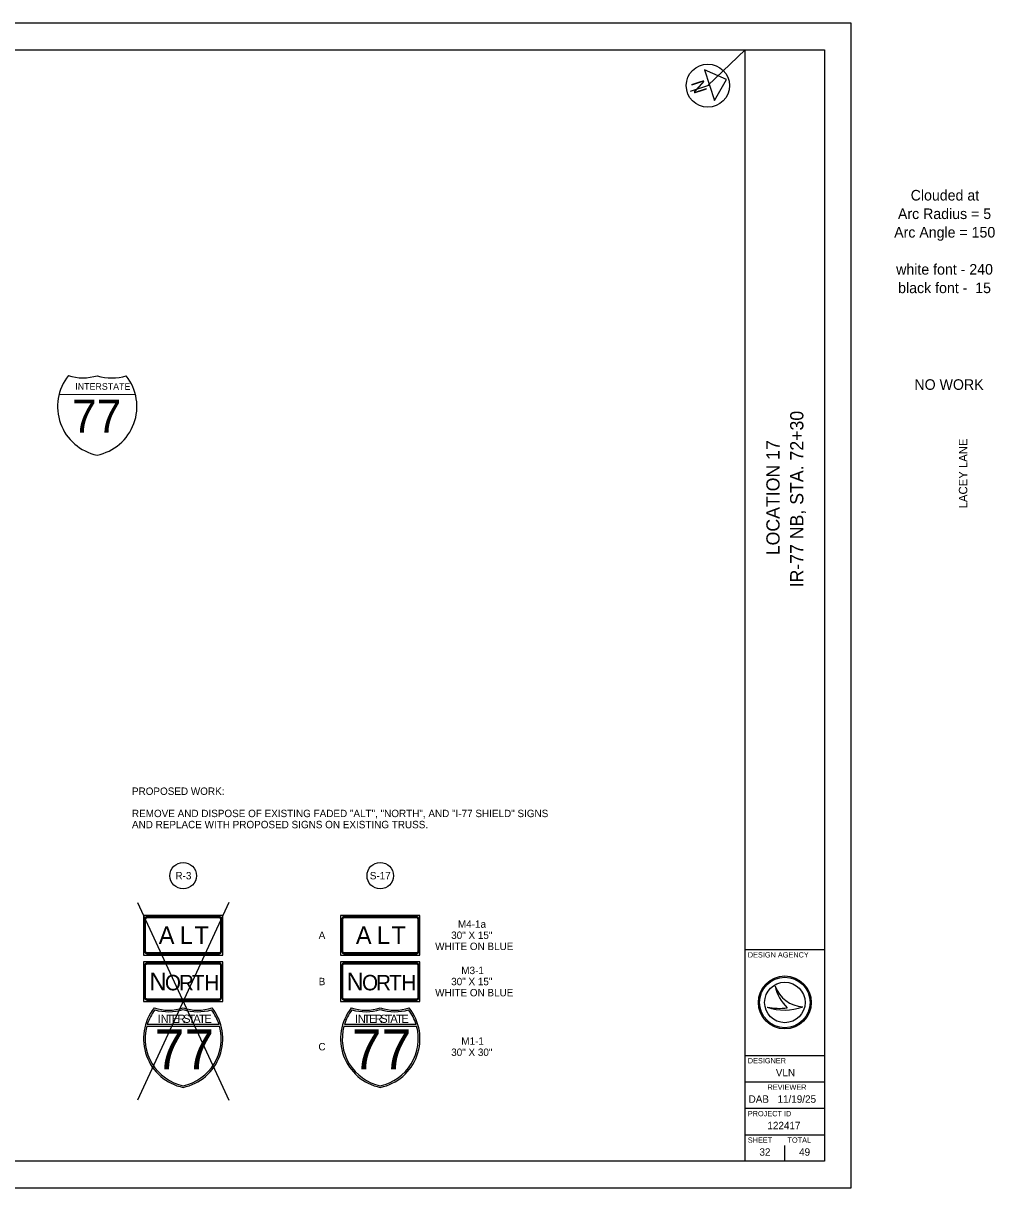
# Model space of a CAD drawing. Extents: x 0 to 734, y 0 to 440.
# Drawn here: x 367.2 to 734.3, y 0 to 440 of the extents above; entities that cross this region are included whole.
import ezdxf

# ---------------------------------------------------------------- set-up
doc = ezdxf.new("R2010")
doc.units = 0
for name, color, linetype in [('Default', 7, 'Continuous'), ('SC_Scratch1', 7, 'Continuous'), ('SH_Border', 7, 'Continuous'), ('SH_Cut_Line', 7, 'Continuous'), ('SH_Data', 7, 'Continuous'), ('SH_Masking', 7, 'Continuous'), ('SH_Text', 7, 'Continuous'), ('SN_P_Text', 7, 'Continuous'), ('SN_X_Public', 7, 'Continuous')]:
    doc.layers.add(name, color=color, linetype=linetype)

msp = doc.modelspace()

# ---------------------------------------------------------------- linework, layer by layer
at = {"layer": 'Default'}
for p, q in [((442.58, 102.91), (412.58, 102.91)), ((412.58, 102.91), (412.58, 87.91)), ((413.1, 101.66), (413.1, 89.16)), ((413.41, 89.16), (413.41, 101.66)), ((441.33, 102.39), (413.83, 102.39)), ((413.83, 102.08), (441.33, 102.08)), ((441.75, 101.66), (441.75, 89.16)), ((442.06, 89.16), (442.06, 101.66)), ((442.58, 87.91), (442.58, 102.91)), ((517.09, 102.91), (487.09, 102.91)), ((487.09, 102.91), (487.09, 87.91)), ((487.61, 101.66), (487.61, 89.16)), ((487.92, 89.16), (487.92, 101.66)), ((515.84, 102.39), (488.34, 102.39)), ((488.34, 102.08), (515.84, 102.08)), ((516.25, 101.66), (516.25, 89.16)), ((516.57, 89.16), (516.57, 101.66)), ((517.09, 87.91), (517.09, 102.91)), ((441.33, 88.74), (413.83, 88.74)), ((413.83, 88.43), (441.33, 88.43)), ((515.84, 88.74), (488.34, 88.74)), ((488.34, 88.43), (515.84, 88.43)), ((412.58, 87.91), (442.58, 87.91)), ((442.58, 85.41), (412.58, 85.41)), ((412.58, 85.41), (412.58, 70.41)), ((413.1, 84.16), (413.1, 71.66)), ((413.41, 71.66), (413.41, 84.16)), ((441.33, 84.89), (413.83, 84.89)), ((413.83, 84.58), (441.33, 84.58)), ((441.75, 84.16), (441.75, 71.66)), ((442.06, 71.66), (442.06, 84.16)), ((442.58, 70.41), (442.58, 85.41)), ((487.09, 87.91), (517.09, 87.91)), ((517.09, 85.41), (487.09, 85.41)), ((487.09, 85.41), (487.09, 70.41)), ((487.61, 84.16), (487.61, 71.66)), ((487.92, 71.66), (487.92, 84.16)), ((515.84, 84.89), (488.34, 84.89)), ((488.34, 84.58), (515.84, 84.58)), ((516.25, 84.16), (516.25, 71.66)), ((516.57, 71.66), (516.57, 84.16)), ((517.09, 70.41), (517.09, 85.41)), ((412.58, 70.41), (442.58, 70.41)), ((441.33, 71.24), (413.83, 71.24)), ((413.83, 70.93), (441.33, 70.93)), ((487.09, 70.41), (517.09, 70.41)), ((515.84, 71.24), (488.34, 71.24)), ((488.34, 70.93), (515.84, 70.93)), ((441.14, 61.66), (414.02, 61.66)), ((515.65, 61.66), (488.53, 61.66)), ((413.84, 61.04), (441.32, 61.04)), ((488.35, 61.04), (515.83, 61.04))]:
    msp.add_line(p, q, dxfattribs=at)
for centre, radius, start, end in [((413.83, 101.66), 0.729, 90, 180), ((413.83, 101.66), 0.417, 90, 180), ((441.33, 101.66), 0.729, 0, 90), ((441.33, 101.66), 0.417, 0, 90), ((488.34, 101.66), 0.729, 90, 180), ((488.34, 101.66), 0.417, 90, 180), ((515.84, 101.66), 0.729, 0, 90), ((515.84, 101.66), 0.417, 0, 90), ((413.83, 89.16), 0.729, 180, 270), ((413.83, 89.16), 0.417, 180, 270), ((441.33, 89.16), 0.729, 270, 0), ((441.33, 89.16), 0.417, 270, 0), ((488.34, 89.16), 0.729, 180, 270), ((488.34, 89.16), 0.417, 180, 270), ((515.84, 89.16), 0.729, 270, 0), ((515.84, 89.16), 0.417, 270, 0), ((413.83, 84.16), 0.729, 90, 180), ((413.83, 84.16), 0.417, 90, 180), ((441.33, 84.16), 0.729, 0, 90), ((441.33, 84.16), 0.417, 0, 90), ((488.34, 84.16), 0.729, 90, 180), ((488.34, 84.16), 0.417, 90, 180), ((515.84, 84.16), 0.729, 0, 90), ((515.84, 84.16), 0.417, 0, 90), ((413.83, 71.66), 0.729, 180, 270), ((413.83, 71.66), 0.417, 180, 270), ((441.33, 71.66), 0.729, 270, 0), ((441.33, 71.66), 0.417, 270, 0), ((488.34, 71.66), 0.729, 180, 270), ((488.34, 71.66), 0.417, 180, 270), ((515.84, 71.66), 0.729, 270, 0), ((515.84, 71.66), 0.417, 270, 0), ((431.33, 56.28), 18.75, 141.669, 258.4631), ((431.33, 56.28), 18.12, 142.9958, 162.7367), ((422.1, 85.84), 18.75, 253.0091, 286.9909), ((422.05, 85.86), 19.37, 254.4393, 286.5745), ((423.83, 56.28), 18.75, 281.537, 38.3311), ((433.06, 85.84), 18.75, 253.0091, 286.9909), ((433.11, 85.86), 19.37, 253.4255, 285.5607), ((423.83, 56.28), 18.12, 17.2633, 37.0042), ((505.84, 56.28), 18.75, 141.669, 258.4631), ((505.84, 56.28), 18.12, 142.9958, 162.7367), ((496.61, 85.84), 18.75, 253.0091, 286.9909), ((496.56, 85.86), 19.37, 254.4393, 286.5745), ((498.34, 56.28), 18.75, 281.537, 38.3311), ((507.57, 85.84), 18.75, 253.0091, 286.9909), ((507.61, 85.86), 19.37, 253.4255, 285.5607), ((498.34, 56.28), 18.12, 17.2633, 37.0042), ((431.33, 56.27), 18.12, 164.7533, 258.0706), ((423.83, 56.27), 18.12, 281.9295, 15.2468), ((505.83, 56.27), 18.12, 164.7533, 258.0706), ((498.34, 56.27), 18.12, 281.9295, 15.2468)]:
    msp.add_arc(centre, radius, start, end, dxfattribs=at)
at = {"layer": 'SC_Scratch1'}
msp.add_line((625.9, 416.45), (640, 430), dxfattribs=at)
at = {"layer": 'SH_Border'}
for p, q in [((640, 10), (640, 430)), ((640, 90), (670, 90)), ((640, 50), (670, 50)), ((640, 40), (670, 40)), ((640, 30), (670, 30)), ((640, 20), (670, 20))]:
    msp.add_line(p, q, dxfattribs=at)
msp.add_lwpolyline([(30, 430), (670, 430), (670, 10), (30, 10)], close=True, dxfattribs=at)
at = {"layer": 'SH_Cut_Line'}
msp.add_lwpolyline([(0, 0), (680, 0), (680, 440), (0, 440)], close=True, dxfattribs=at)
at = {"layer": 'SH_Data'}
for p, q in [((651.35, 76.19), (651.35, 76.19)), ((648.34, 68.19), (648.34, 68.19)), ((655, 70), (655, 70)), ((661.75, 68.37), (661.75, 68.37)), ((647.5, 13.5), (647.5, 13.5)), ((655, 10), (655, 16))]:
    msp.add_line(p, q, dxfattribs=at)
for radius in [10, 9.54, 9.54, 7.64]:
    msp.add_circle((655, 70), radius, dxfattribs=at)
for centre, radius, start, end in [((662.32, 79.95), 11.6, 198.9257, 198.9319), ((666.93, 79.4), 15.91, 191.6379, 191.6421), ((662.32, 79.95), 11.6, 198.9319, 267.1657), ((666.93, 79.4), 15.91, 191.6421, 226.0947), ((654.79, 87.4), 20.26, 251.4576, 290.0832), ((652.96, 93.09), 25.32, 259.4964, 259.4995), ((654.79, 87.4), 20.26, 251.4527, 251.4576), ((652.96, 93.09), 25.32, 259.4995, 276.6672)]:
    msp.add_arc(centre, radius, start, end, dxfattribs=at)
at = {"layer": 'SH_Masking'}
msp.add_circle((625.9, 416.45), 8.16, dxfattribs=at)
at = {"layer": 'SH_Text'}
for p, q in [((632.96, 418.77), (624.6, 422.46)), ((624.6, 422.46), (628.42, 410.84)), ((628.42, 410.84), (632.96, 418.77)), ((626.51, 416.65), (619.2, 414.25)), ((444.83, 107.79), (410.33, 33.04)), ((410.33, 107.79), (444.83, 33.04))]:
    msp.add_line(p, q, dxfattribs=at)
for centre, radius in [((625.9, 416.45), 8.16), ((427.58, 117.91), 5), ((502.09, 117.91), 5)]:
    msp.add_circle(centre, radius, dxfattribs=at)
at = {"layer": 'SN_X_Public'}
msp.add_line((380.69, 299.84), (409.55, 299.75), dxfattribs=at)
for centre, start, end in [((398.86, 295.19), 141.4867, 258.2807), ((389.72, 324.78), 252.8268, 286.8086), ((391.36, 295.21), 281.3547, 38.1487), ((400.68, 324.74), 252.8268, 286.8086)]:
    msp.add_arc(centre, 18.75, start, end, dxfattribs=at)

# ---------------------------------------------------------------- texts
at = {"layer": 'Default'}
for s, height, p in [('A', 6.67, (418.35, 92.08)), ('L', 6.67, (426.28, 92.08)), ('T', 6.67, (431.81, 92.08)), ('A', 6.67, (492.85, 92.08)), ('L', 6.67, (500.79, 92.08)), ('T', 6.67, (506.32, 92.08)), ('N', 6.67, (414.85, 74.58)), ('O', 5.83, (420.69, 74.58)), ('R', 5.83, (425.99, 74.58)), ('T', 5.83, (430.91, 74.58)), ('H', 5.83, (435.58, 74.58)), ('N', 6.67, (489.36, 74.58)), ('O', 5.83, (495.19, 74.58)), ('R', 5.83, (500.5, 74.58)), ('T', 5.83, (505.41, 74.58)), ('H', 5.83, (510.09, 74.58)), ('I', 3.12, (417.97, 62.29)), ('N', 3.12, (419.09, 62.29)), ('T', 3.12, (421.28, 62.29)), ('E', 3.12, (423.31, 62.29)), ('R', 3.12, (425.44, 62.29)), ('S', 3.12, (427.56, 62.29)), ('T', 3.12, (429.59, 62.29)), ('A', 3.12, (431.38, 62.29)), ('T', 3.12, (433.56, 62.29)), ('E', 3.12, (435.59, 62.29)), ('I', 3.12, (492.48, 62.29)), ('N', 3.12, (493.6, 62.29)), ('T', 3.12, (495.79, 62.29)), ('E', 3.12, (497.82, 62.29)), ('R', 3.12, (499.95, 62.29)), ('S', 3.12, (502.07, 62.29)), ('T', 3.12, (504.1, 62.29)), ('A', 3.12, (505.88, 62.29)), ('T', 3.12, (508.07, 62.29)), ('E', 3.12, (510.1, 62.29)), ('7', 15, (416.85, 44.79)), ('7', 15, (428.1, 44.79)), ('7', 15, (491.36, 44.79)), ('7', 15, (502.61, 44.79))]:
    msp.add_text(s, height=height, dxfattribs=at).set_placement(p)
at = {"layer": 'SH_Data'}
for s, p in [('IR-77 NB, STA. 72+30', (662, 226.85)), ('LOCATION 17', (653, 238.99))]:
    msp.add_text(s, height=5, rotation=90, dxfattribs=at).set_placement(p)
for s, height, p in [('DESIGN AGENCY', 2, (641, 87)), ('DESIGNER', 2, (641, 47)), ('VLN', 2.8, (651.58, 42.1)), ('REVIEWER', 2, (648.44, 37)), ('DAB', 2.8, (641.3, 32.1)), ('11/19/25', 2.8, (652.22, 32.1)), ('PROJECT ID', 2, (641, 27)), ('122417', 2.8, (648.4, 22.1)), ('SHEET', 2, (641, 17)), ('TOTAL', 2, (656, 17)), ('32', 2.8, (645.39, 12.1)), ('49', 2.8, (660.38, 12.1))]:
    msp.add_text(s, height=height, dxfattribs=at).set_placement(p)
at = {"layer": 'SH_Text'}
for s, height, rotation, p in [('N', 4.97, 288.1972, (619.45, 417.5)), ('LACEY LANE', 3.2, 90, (723.96, 256.7))]:
    msp.add_text(s, height=height, rotation=rotation, dxfattribs=at).set_placement(p)
for s, height, p in [('Clouded at ', 4, (702.56, 373.03)), ('Arc Radius = 5', 4, (697.74, 366.03)), ('Arc Angle = 150', 4, (696.31, 359.03)), ('white font - 240', 4, (697.07, 345.03)), ('black font -  15', 4, (697.82, 338.03)), ('NO WORK', 4, (703.97, 301.49)), ('PROPOSED WORK:', 2.8, (408.23, 148.43)), ('REMOVE AND DISPOSE OF EXISTING FADED "ALT", "NORTH", AND "I-77 SHIELD" SIGNS', 2.8, (408.23, 140.03)), ('AND REPLACE WITH PROPOSED SIGNS ON EXISTING TRUSS.', 2.8, (408.23, 135.83)), ('R-3', 2.8, (424.67, 116.51)), ('S-17', 2.8, (498.12, 116.51))]:
    msp.add_text(s, height=height, dxfattribs=at).set_placement(p)
at = {"layer": 'SN_P_Text'}
for s, p in [('A', (478.8, 94.01)), ('30" X 15"', (528.89, 94.01)), ('M4-1a', (531.44, 98.21)), ('WHITE ON BLUE', (522.83, 89.81)), ('B', (478.81, 76.51)), ('30" X 15"', (528.89, 76.51)), ('M3-1', (532.71, 80.71)), ('WHITE ON BLUE', (522.83, 72.31)), ('C', (478.71, 51.89)), ('M1-1', (532.71, 53.99)), ('30" X 30"', (528.89, 49.79))]:
    msp.add_text(s, height=2.8, dxfattribs=at).set_placement(p)
at = {"layer": 'SN_X_Public'}
for s, height, p in [('INTERSTATE', 2.5, (386.82, 301.54)), ('77', 12.5, (385.55, 285.3))]:
    msp.add_text(s, height=height, rotation=359.8177, dxfattribs=at).set_placement(p)

doc.saveas('drawing.dxf')
